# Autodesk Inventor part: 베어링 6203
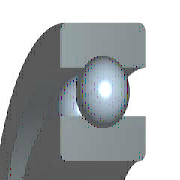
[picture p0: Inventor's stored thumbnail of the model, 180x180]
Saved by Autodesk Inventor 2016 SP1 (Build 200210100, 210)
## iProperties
Created: 2012-02
Part Number: 베어링 6203
Material: 강철, 연강
Description: 깊은 그루브 볼 베어링
Document SubType Name: Modeling
Standard: KS B 2023
Designer: mduedu
Standards Organization: KS
Language: ko-KR
Size Designation: 6203 - 17 x 40 x 12
Categories: <MemberInstance><Categories><Category DisplayName="샤프트 부품" InternalName="7f7aeb1f-a693-4053-b835-cee3144e0d98" Mnemonic="SHFT"><Category DisplayName="베어링" Inter
Density: 1 g/cm^3
Appearance: 노란색
IsCustomPart: 1
Author: mduedu
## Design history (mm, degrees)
sketch "스케치" dims "d0" = 5.98 (= -0.26 x WD + 0.26 x BD)
  geometry: L1 (3.01, 14.25)-(8.99, 14.25); L2 (6, 14.25)-(6, 11.26); L3 (6, 14.25)-(6, 17.24); L4 (3.778, 12.249)-(0, 12.249); L5 (0, 8.5)-(12, 8.5); L6 (3.778, 16.251)-(0, 16.251); L7 (0, 20)-(12, 20); L8 (12, 8.5)-(12, 12.249); L9 (8.222, 12.249)-(12, 12.249); L10 (8.222, 16.251)-(12, 16.251); L11 (12, 20)-(12, 16.251); L12 (-1.4, 0)-(8.4, 0) reference; L13 (0, -0.3)-(0, 5.3) reference
  constraints: 22 end point, 4 point on line, 2 collinear, 2 perpendicular, 2 symmetric about line, 1 midpoint, 1 parallel, 14 other
  dimensions: "d9" = 17 diameter of L5 L12 (= WD); "d11" = 40 diameter of L7 L12 (= BD); "d12" = 12 distance between parallel lines of L8 L13 (= KB); "d13" = 24.498 diameter of L9 L12 (= 0.326 x BD + 0.674 x WD)
revolve "본체" stored, may be unused: angle "d6" = 90 deg
revolve "볼" stored, may be unused: angle "d7" = 90 deg
pattern_circular "IDS_ARRAYBALL[SIMPL:T]" dims angle "d3" = 360 deg
body "Solid1"
fillet "모깎기1" dims "d1" = 0.6 (= KRS)
other parameters: "WD" = 17 [user parameter; used in 5 equation terms], "BD" = 40 [user parameter; used in 5 equation terms], "KB" = 12 [user parameter; used in 1 equation term], "KRS" = 0.6 [user parameter; used in 1 equation term], "d4" = 0, "d5" = 0, "d8" = 0, "d14" = 0, "d15" = 0, "BBA" = 0 [user parameter], "BC0" = 4750000 [user parameter], "BC" = 9560000 [user parameter], "WR" = 8.5 (= 0.5 x WD) [user parameter]
